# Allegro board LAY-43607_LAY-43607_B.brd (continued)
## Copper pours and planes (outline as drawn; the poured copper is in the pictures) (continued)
(no net) on TOP: 103.49,97.58 104.05,97.02 105.83,97.02 105.9,97.1 105.9,100.09 106.18,100.37 107.71,100.37 109.33,102 109.33,104.91 107.83,106.41 101.71,106.41 100.93,105.63 100.93,101.42 99.81,100.3 99.81,100.02 100.04,99.79 103.21,99.79 103.49,99.51
(no net) on TOP: 110.25,95.32 114.72,95.32 114.74,95.29 115.28,95.29 115.35,95.22 115.35,93.59 115.33,93.57 112.15,93.57 112.13,93.54 112.13,92.93 111.8,92.93 111.77,92.91 111.77,92.5 111.75,92.47 111.57,92.47 111.52,92.52 111.52,93.57 111.16,93.92 110.35,93.92 110.25,94.02
(no net) on TOP: 110.2,100.09 110.2,97.88 110.75,97.32 112.53,97.32 112.61,97.4 112.61,100.09 112.38,100.32 110.42,100.32
(no net) on TOP: 115.02,95.72 115.35,96.05 115.35,98.24 115.07,98.52 113.12,98.52 112.98,98.38 112.98,98 112.84,97.86 112.84,96.99 109.99,96.99 109.98,96.98 109.97,96.99 109.51,96.99 109.51,96.84 109.43,96.77 109.43,92.4 110.37,92.4 110.63,92.14 111.29,92.14 111.31,92.17 111.31,93.34 110.96,93.69 110.25,93.69 109.92,94.02 109.92,95.62 110.02,95.72
(no net) on TOP: 106.23,92.78 107.33,92.78 107.35,92.8 108.72,92.8 109,92.52 109,91.51 109.31,91.2 112.28,91.2 112.28,93.13 112.39,93.25 114.98,93.25 115.07,93.16 115.07,90.37 115,90.29 113.42,90.29 113.27,90.14 113.27,90.11 113.02,89.86 110.88,89.86 110.6,89.58 110.6,85.97 110.45,85.82 105.37,85.82 105.29,85.89 105.29,86.17 105.27,86.2 105.27,88.59 105.52,88.59 105.95,89.02 105.95,91.41 105.57,91.79 104.79,91.79 104.71,91.86 104.71,92.02 104.79,92.09 105.14,92.09 105.19,92.14 105.19,92.47 105.24,92.52 105.98,92.52
(no net) on BOTTOM: 112.62,82.55 112.62,81.76 112.92,81.46 112.92,78.28 113.5,77.71 118.52,77.71 118.88,78.07 118.88,79.86 118.49,80.25 115.97,80.25 115.26,80.96 113.98,80.96 113.69,81.25 113.69,82.6 113.63,82.66 112.72,82.66 112.62,82.55
CPU_LVDD on BOTTOM: 56.63,57.93 56.63,58.69 56.8,58.87 56.8,59.66 56.8,59.67 54.68,59.67 54.6,59.58 54.6,58.18 54.98,57.8 56.5,57.8
CPU_LVDD on L5_PWR: 62.98,51.33 57.9,51.33 54.47,54.75 54.52,54.75 54.52,58.94 54.72,59.15 56.55,59.15 56.88,58.82 56.88,57.68 62.34,52.21 62.98,52.21 63.23,51.96 63.23,51.58
CPU_SVDD on BOTTOM: 44.38,40.35 44.38,38.93 44.56,38.75 48.12,38.75 48.37,39.01 48.37,39.64 48.24,39.78 45.57,39.78 45.2,40.15 45.2,40.17 44.84,40.53 44.56,40.53
CPU_SVDD on L4_INT_2: 63.47,47.88 63.47,42.9 62.71,42.15 62.71,38.69 61.69,37.66 59.29,37.66 58.8,38.16 49.4,38.16 48.92,37.68 48.92,37.66 45.83,37.66 44.98,38.52 44.67,38.52 44.44,38.75 44.44,39.97 45.29,40.82 45.29,43.4 45.98,44.1 53.68,44.1 57.12,40.66 59.09,40.66 59.38,40.95 59.38,49.82 59.45,49.89 60.76,49.89 60.87,49.78 60.87,49.78 61.18,49.47 61.18,48.22 61.53,47.88
CPU_USB_HVDD on L4_INT_2: 67.65,51.24 67.65,50.68 67.04,50.07 65.77,50.07 65.02,50.08 63.66,51.45 63.66,59.94 63.19,60.41 61.49,60.41 60.98,59.9 60.98,51.5 60.99,51.49 60.99,50.53 61.62,49.9 61.62,49.14 61.85,48.91 61.85,48.91 62.51,48.25 63.93,48.25 64.15,48.04 64.44,48.04 64.44,48.04 67.11,48.04 69.35,50.27 69.35,51.24
CPU_USB_SDVDD on L4_INT_2: 67.24,50.8 67.24,52.15 67.24,52.15 66.63,52.76 66.63,59.9 66.19,60.33 64.52,60.33 64.24,60.06 64.24,59.92 64.23,59.91 64.23,51.55 65.28,50.5 66.93,50.5
CPU_USB_SVDD on L4_INT_2: 69.96,52.18 69.96,53.7 69.19,54.46 69.19,55.27 69.63,55.71 69.63,59.45 69.24,59.84 68.91,60.17 67.84,60.17 67.3,59.64 67.3,52.8 67.62,52.49 67.62,51.67 67.67,51.62 69.4,51.62
CPU_VDD on TOP: 87.01,51.67 92.1,51.67 92.5,52.07 92.5,55.76 91.94,56.32 87.6,56.32 86.85,55.57 86.85,51.82
CPU_VDD on TOP: 96,55.14 96,34.05 96.89,33.16 101.2,33.16 101.84,33.8 101.84,55.14 101.33,55.64 96.51,55.64
CPU_VDD on TOP, BOTTOM: 86.88,35.78 86.88,33.8 90.33,33.8 90.33,35.78
CPU_VDD on BOTTOM: 87.85,51.65 91.67,51.65 92.12,52.1 92.12,55.16 92.01,55.27 92.01,55.31 90.97,56.35 88.53,56.35 88.52,56.37 87.32,56.37 87.3,56.39 86.92,56.01 84.22,56.01 83.98,55.77 83.98,53.87 84.11,53.74 87.13,53.74 87.18,53.79 87.65,53.79 87.85,53.59
CPU_VDD on BOTTOM: 101.71,55.52 101.09,55.52 100.95,55.65 100.95,56.37 102.4,57.82 104.97,57.82 105.13,57.98 105.13,59.59 104.64,60.07 101.5,60.07 99.54,58.11 99.54,56.59 99.25,56.59 98.18,55.52 96.76,55.52 95.84,54.6 95.84,35.09 96.2,34.74 101.59,34.74 102.12,35.27 102.12,55.11
CPU_VDD on BOTTOM: 43.42,40.78 43.17,41.04 40.46,41.04 40.46,41.04 39.74,41.04 39.49,40.78 39.49,37.96 39.49,37.96 39.49,36.77 40.37,35.89 40.76,35.89 41.13,35.53 42.86,35.53 43.42,36.09
CPU_VDD on L4_INT_2: 91.67,51.03 84.5,51.03 83.94,51.59 83.94,55.21 82.59,56.57 78.81,56.57 74.25,61.13 74.25,61.91 74.05,62.1 71.6,62.1 71.6,62.07 70.32,60.79 61.79,60.79 60.48,62.1 57.93,62.1 57.57,61.74 57.57,61.72 55.68,59.84 50.71,59.84 47.2,56.33 47.2,49.35 44.53,46.68 44.53,41.53 43.9,40.91 43.9,38.59 44.4,38.09 45.06,38.09 45.44,37.71 45.44,35.06 45.09,34.71 40.16,34.71 39.38,35.49 39.38,43.51 40.45,44.59 40.45,49.19 40.75,49.49 42.71,49.49 43.49,50.27 43.49,53.03 42.67,53.86 42.67,57.96 44.14,59.43 44.16,59.43 48.3,63.56 53.61,63.56 57.69,67.64 57.7,67.63 66.06,67.63 66.07,67.65 66.07,66.18 70.53,66.18 71.99,67.63 78.52,67.63 84.79,61.36 89.13,61.36 89.13,59.41 92,56.54 92,55.33 92.52,54.81 92.52,51.88
CPU_VDD on L5_PWR: 69,40.05 58.64,40.05 58.61,40.08 58.61,43.3 57.94,43.97 57.94,49.18 58.57,49.8 59.34,49.8 59.5,49.95 59.5,50.77 59.78,51.05 59.79,51.03 63.15,51.03 63.55,50.64 70.68,50.64 71.5,51.45 79.58,51.45 79.66,51.37 79.66,47.61 79.81,47.46 87.2,47.46 87.2,51.48 87.08,51.6 87.28,51.81 87.28,53.2 86.57,53.92 85,53.92 84.97,53.89 84.24,53.89 83.88,54.25 83.88,56.79 84.41,57.32 100.77,57.32 102.14,55.95 102.14,48.29 101.12,47.27 101.12,41.05 101.76,40.41 101.76,32.33 101.64,32.2 90.74,32.2 89.6,33.34 86.84,33.34 82.98,37.2 80.9,37.2 75.35,42.75 70.82,42.75 70.74,42.83 70.74,43.24 70.7,43.28 69.79,43.28 69.13,42.63 69.13,40.18
CPU_VDD_I on TOP: 108.57,48.51 110.16,48.51 110.16,41.78 109.08,41.78 109.08,33.67 108.57,33.16 103.24,33.16 102.47,33.93 102.47,56.66 102.98,57.17 107.81,57.17 108.57,56.41
CPU_VDD_I on BOTTOM: 108.56,48.48 110.14,48.48 110.14,41.75 109.06,41.75 109.06,33.64 108.73,33.31 103.04,33.31 102.46,33.9 102.46,56.63 102.97,57.14 107.79,57.14 108.56,56.38
CPU_XVDD on TOP: 49.13,53.87 48.07,53.87 47.76,54.17 46.97,54.17 46.82,54.03 46.82,53.56 47.1,53.29 47.1,53.29 47.1,50.31 47.23,50.18 47.74,50.18 47.99,50.44 47.99,50.94 48.5,51.45 49.26,51.45 49.39,51.58 49.39,53.61 49.14,53.86
CPU_XVDD on TOP: 45.83,44.72 45.96,44.85 45.96,47.01 45.88,47.08 44.03,47.08 43.67,46.73 43.67,44.87 43.83,44.72
CPU_XVDD on L4_INT_2: 57.41,41.17 57.9,41.17 58.51,41.17 58.69,41.35 58.69,50.26 58.66,50.28 58.66,52.92 57.87,53.71 47.77,53.71 47.77,50.13 47.7,50.07 47.7,46.98 47.51,46.79 44.86,46.79 44.71,46.64 44.71,45.48 44.82,45.36 47.35,45.36 47.35,44.44 54.14,44.44
DDR_VTT on TOP: 36.73,19.5 36.73,20.23 39.85,20.23 39.85,18.37 39.02,18.37 39.02,17.29 38.53,17.29 38.53,3.6 53.8,3.6 53.8,1.65 36.94,1.65 36.94,19.5
DDR_VTT on TOP: 80.1,77.69 83.4,77.69 83.86,77.23 83.86,74.11 83.45,73.7 80.25,73.7 79.94,74.01 79.94,77.54
DDR_VTT on BOTTOM: 36.83,20.23 39.85,20.23 39.85,18.37 39.02,18.37 39.02,17.29 38.53,17.29 38.53,3.6 50.88,3.6 50.88,3.51 51.37,3.51 51.49,3.38 51.49,2.77 51.44,2.72 51.44,2.21 50.88,1.65 36.94,1.65 36.94,18.43 36.79,18.43 36.79,20.19
DDR_VTT on L4_INT_2: 77.99,73.35 75.73,73.35 75.6,73.47 75.6,73.93 75.78,74.11 77.38,74.11 77.53,74.26 77.53,82.85 76.02,84.36 76.02,84.42 74.29,86.15 74.29,90.37 72.74,91.93 66.19,91.93 64.28,93.83 64.28,94.54 33.01,94.54 31.48,93.01 21.71,93.01 20.53,91.84 20.56,91.81 20.56,77.78 17.39,74.61 17.39,58.82 18.53,57.68 18.53,53.61 17.39,52.47 17.39,47.13 19.16,45.36 19.16,41.03 17.39,39.26 17.39,15.05 18.26,14.19 35.88,14.19 36.04,14.35 36.04,19 36.89,19.85 39.46,19.85 39.69,19.63 39.69,9.66 39.52,9.49 39.79,9.22 39.79,5.25 38.31,3.77 23.12,3.77 18.77,8.12 14.17,8.12 13.46,8.84 13.46,16.75 13.23,16.97 13.23,77.01 13.85,77.63 16.42,77.63 17.38,78.59 17.38,93.13 28.64,104.39 64.04,104.39 64.08,104.35 68.37,104.35 81.12,91.6 85.85,91.6 87.38,90.07 87.38,85.42 86.15,84.18 86.15,83.19 84.8,81.84 84.8,74.23 84.25,73.69 82.77,73.69 82.69,73.6 78.24,73.6
FA_VL on L3_INT_1: 62.47,53.74 61.2,53.74 60.18,52.72 60.18,43.17 58.06,41.04 57.52,41.04 57.42,40.94 57.42,40.05 57.6,39.87 57.87,39.87 56.5,38.5 46.04,38.5 45.46,39.07 40.55,39.07 40.02,38.54 40.02,36.34 40.52,35.83 41.14,35.83 41.14,35.83 57.82,35.83 61.96,39.97 61.96,51.96 62.6,52.6 62.6,53.61
GVDD on TOP: 80.25,73.25 83.55,73.25 84.01,72.79 84.01,68.98 83.96,68.93 80.2,68.93 80.1,69.03 80.1,73.09
GVDD on TOP: 38.72,26.18 40.37,26.18 40.5,26.31 43.8,26.31 44.56,25.54 44.56,23.51 43.67,22.62 38.85,22.62 38.59,22.88 38.59,26.05
GVDD on TOP: 100.14,23.56 96.94,23.56 96.05,24.45 96.05,30.14 96.12,30.22 100.49,30.22 100.75,29.96 100.75,27.83 100.62,27.7 100.62,24.05
GVDD on TOP: 34.58,16.19 34.58,1.65 36.46,1.65 36.46,16.26 36.45,16.26 36.28,16.44 34.82,16.44
GVDD on BOTTOM: 100.75,26.08 96.17,26.08 95.97,26.28 95.97,30.42 96.25,30.7 100.37,30.7 100.8,30.27 100.8,26.13
GVDD on L2_GND: 58.75,39.75 58.32,40.18 54.59,40.18 54.49,40.29 54.49,40.29 53.82,40.96 46.55,40.96 44,38.42 44,35.25 43.55,34.8 43.75,34.6 43.75,30.21 43.74,30.22 38.66,30.22 37.95,29.51 37.95,22.93 38.14,22.74 39.07,22.74 39.27,22.54 39.27,19.82 39.3,19.82 39.3,16.65 37.45,16.65 36.69,15.89 35.55,15.89 35.04,15.38 35.04,5.73 35.8,4.97 38.85,4.97 39.3,4.51 39.3,3.32 40.32,2.3 101.78,2.3 101.78,6.41 104.21,8.84 104.21,18.82 103.56,19.47 103.56,19.82 103.56,20.14 99.82,23.89 99.82,28.81 99.32,29.31 94.35,29.31 93.28,30.38 93.28,30.38 92.74,30.92 89.65,30.92 89.63,30.9 86.27,34.26 86.1,34.26 84.96,35.39 84.96,37.06 81.62,40.41 79.48,40.41 79.02,39.95 77.93,39.95 77.47,40.41 73.58,40.41 73.06,39.89 73.06,37.75 69.71,37.75 68.05,39.4 58.88,39.4 58.75,39.54
GVDD on L4_INT_2: outline of 84 points within 25.49,21.61 83.29,93.79
OVDD on TOP: 57.85,81.53 61.15,81.53 61.61,81.07 61.61,77.94 61.2,77.54 58,77.54 57.69,77.84 57.69,81.37
OVDD on TOP: 13.84,80.85 15.12,80.85 15.12,80.17 16.67,78.61 16.67,71.5 17.28,70.89 17.28,58.83 17.62,58.49 17.62,57.57 17.53,57.48 15.21,57.48 15.12,57.57 15.12,68.36 13.84,69.63
OVDD on BOTTOM: 88.58,38.63 88.38,38.83 86.42,38.83 86.12,39.13 86.12,39.69 86.47,40.05 87.77,40.05 87.95,40.23 87.95,41.67 87.59,42.03 86.22,42.03 85.86,42.38 85.86,45.15 86.04,45.33 94.12,45.33 95.08,44.37 95.08,38.57 95.46,38.19 95.46,35.06 95.2,34.8 94.1,34.8 93.71,35.19 93.71,36.7 93.74,36.72 93.74,37.99 92.19,37.99 90.94,39.23 90.13,39.23 89.6,38.7 89.6,36.36 89.57,36.34 88.76,36.34 88.58,36.52
OVDD on BOTTOM: 25.27,84.73 25.01,84.99 20.55,84.99 19.16,86.38 14.32,86.38 13.86,85.91 13.86,78.99 14,78.85 15.64,78.85 16.13,79.34 16.13,84.35 16.42,84.64 18.95,84.64 22.12,81.47 22.12,78.45 22.47,78.1 24.72,78.1 25.27,78.65
OVDD on BOTTOM: 84.6,51.91 85.72,51.91 85.92,51.7 86.75,51.7 86.95,51.91 86.95,53.22 86.62,53.55 85.07,53.55 84.36,52.84 84.36,52.19 84.6,51.95
OVDD on BOTTOM: 32.36,67.79 32.57,67.59 33.33,67.59 33.36,67.57 33.63,67.57 34.1,68.03 34.1,70.47 34.1,70.47 34.4,70.77 34.4,71.44 34.16,71.67 33.51,71.67 33.36,71.53 33.36,70.98 32.74,70.98 32.36,70.6
OVDD on BOTTOM: 88.77,88.98 84.16,88.98 79.06,94.07 74.13,94.07 73.34,94.86 73.34,97.43 73.7,97.79 73.7,98.69 73.83,98.82 76.37,98.82 76.44,98.75 76.44,98.17 76.9,97.7 79.41,97.7 79.5,97.8 79.5,98.76 79.57,98.83 80.65,98.83 80.73,98.75 80.73,98.05 80.95,97.83 82.59,97.83 82.68,97.91 82.68,98.7 82.84,98.86 83.72,98.86 83.93,98.64 83.93,98.32 84.26,97.99 85.37,97.99 85.62,98.25 85.62,98.61 85.91,98.89 86.68,98.89 86.68,109.13 85.47,110.34 85.47,112.15 86,112.68 87.64,112.68 88.15,112.17 88.15,97.43 87.88,97.16 80.95,97.16 80.75,96.95 80.75,96.35 81.12,95.98 86.77,95.98 86.84,96.05 87.19,96.05 87.53,95.71 87.53,94.94 84.91,92.32 84.91,91.21 85.75,90.38 87.11,90.38 87.16,90.43 88.52,90.43 88.94,90.01 88.94,89.14
OVDD on BOTTOM: 54.01,60.01 55.51,60.01 55.61,60.11 55.61,62.09 54.91,62.79 54.91,67.44 56.63,69.16 56.63,77.04 57.67,78.08 60.63,78.08 60.82,78.27 60.82,82.03 60.67,82.19 54.7,82.19 53.15,80.64 53.15,68.91 52.08,67.84 52.02,67.84 48.99,64.81 48.79,64.61 44.85,64.61 43.29,63.05 42.49,63.05 41.92,62.48 41.92,62.27 41.92,62.27 41.92,61.41 42.02,61.31 42.98,61.31 43.21,61.55 43.21,62 43.36,62.15 44.16,62.15 44.18,62.17 45.12,62.17 45.28,62.33 45.28,62.87 45.3,62.84 46.42,62.84 46.68,62.59 46.68,62.17 46.92,62.17 47.84,61.26 48.96,61.26 49.34,60.88 51.75,60.88 52.87,59.76 53.76,59.76
OVDD on L3_INT_1: 71.23,51.22 71.23,50.82 71.11,50.69 70.47,50.69 69.2,49.42 69.2,46.63 69.84,45.99 69.84,42.05 69.45,41.67 68.44,41.67 67.1,40.34 67.1,29.51 66.49,28.9 44.05,28.9 43.6,29.35 43.6,29.43 41.41,31.61 41.38,31.61 41.38,34.63 41.89,35.15 57.76,35.15 62.44,39.83 62.44,51.83 62.8,52.19 62.8,52.39 63.08,52.67 69.58,52.67 69.58,51.73 69.94,51.38 71.08,51.38
OVDD on L4_INT_2: 86.76,113.45 19.99,113.45 13.85,107.32 13.85,78.61 14.09,78.37 16.38,78.37 16.78,78.77 16.78,95.88 16.72,95.94 25.79,105 68.84,105 74.97,98.88 74.97,98.85 78.22,95.59 78.23,95.59 81.77,92.06 84.72,92.06 86.73,94.07 92.53,94.07 95.94,90.67 95.94,81.18 96.1,81.03 96.1,61.61 96.16,61.55 96.16,56.02 94.79,54.66 94.79,42.2 96.16,40.84 96.16,37.25 105.49,27.92 105.49,20.46 107.55,18.4 107.55,8.07 107.14,7.66 105.76,7.66 103.44,9.98 103.44,26.69 95.04,35.09 95.04,38.51 94.47,39.08 91.07,39.08 90.91,39.24 90.91,43.61 89.05,45.46 85.31,45.46 85.13,45.65 85.13,46.81 84.96,46.99 80.81,46.99 80.49,46.67 80.49,40.32 81.44,39.37 86.4,39.37 88.46,37.32 88.46,33.94 98.59,23.81 98.59,7.73 102.42,3.9 110.86,3.9 112,5.04 112,15.26 113.01,16.27 125.4,16.27 126.51,17.38 126.51,28.78 126.36,28.93 113.95,28.93 100.45,42.44 100.45,55.54 102.17,57.26 102.17,97.93 101.21,98.89 100.44,98.89 97.82,101.51 97.82,110.34 94.22,113.94 86.9,113.94 86.76,113.8
OVDD on L4_INT_2: 52.44,81.87 66.19,81.87 66.63,81.43 66.63,78.81 64.9,77.08 63.91,77.08 63.85,77.02 58.72,77.02 58.17,76.47 58.17,73.71 53.65,69.19 53.65,68.46 52.95,67.77 52.94,67.78 43.8,67.78 42.4,66.38 39.42,66.38 37.56,64.52 37.56,60.97 37.01,60.43 36.08,60.43 35.62,59.96 35.62,53.05 38.38,50.29 38.05,49.97 38.05,42.79 38.84,42 38.84,35.63 40.44,34.02 44.16,34.02 44.16,30.56 38.13,30.56 32.5,36.2 32.5,64.9 32.46,64.94 32.44,64.94 32.44,68.62 32.44,68.62 32.25,68.81 32.25,70.5 32.74,70.98 32.74,71.02 33.33,71.62 45.48,71.62 46.15,72.29 46.15,76.62 46.34,76.8 47.31,76.8 48.52,78.01 51.29,78.01 52.11,78.83 52.11,81.55
OVDD on L5_PWR: outline of 83 points within 77.24,15.97 126.2,74.03
OVDD on L5_PWR: 74.51,98.86 86.36,98.86 87.29,97.93 87.29,96.17 74.79,83.67 67.74,83.67 66.71,82.64 66.71,80.94 66.6,80.84 63.51,80.84 60.64,77.97 58.24,77.97 57.98,78.23 57.98,86.16 58.48,86.66 67.83,86.66 68.11,86.95 68.11,92.47
SW1LX on TOP: 62.72,85.01 62.72,81.84 64.12,81.84 64.63,81.33 64.63,79.69 65.01,79.31 65.26,79.31 65.39,79.43 65.39,80.83 66.03,81.46 66.03,83.23 64.25,85.01
SW2LX on TOP: 62.6,81.07 62.6,78.02 64.87,78.02 65.26,78.42 65.26,78.54 64.25,79.56 64.25,81.07
SW3LX on TOP: 62.72,74.08 63.72,74.08 63.99,74.35 63.99,75.75 64.63,76.38 64.63,77.02 64.25,77.4 62.72,77.4
SW5LX on TOP: 77.8,73.88 77.33,74.35 77.33,75.37 76.82,75.88 76.69,75.88 76.69,72.02 77.05,72.02 77.17,71.9 77.17,70.34 77.24,70.27 79.11,70.27 79.17,70.33 79.18,70.33 79.18,73.72 79.02,73.88
SW6LX on TOP: 77.46,77.15 79.11,77.15 79.11,74.35 77.71,74.35 77.71,75.5 76.95,76.26 76.95,76.64
SW7LX on TOP: 79.03,80.94 77.96,80.94 77.33,80.31 77.33,77.77 79.03,77.77
USB1_ISO_VOUT on TOP (solid shape): 112.61,100.09 112.61,99.45 112.61,99.22 112.61,97.99 112.58,97.96 112.58,97.37 112.53,97.32 110.75,97.32 110.2,97.88 110.2,100.09 110.42,100.32 112.38,100.32
USB1_ISO_VOUT on BOTTOM: 110.35,100.27 110.35,100.22 109.94,99.81 109.94,98.21 110.02,98.14 112.43,98.14 112.43,100.07 112.46,100.09 112.28,100.27
USB1_ISO_VOUT on L3_INT_1: 107.51,100.86 110.08,98.29 112.28,98.29 112.88,98.89 112.88,100.19 112.44,100.63 110.74,100.63 110.28,101.09 110.28,106.66 110.32,106.7 110.32,107.39 109.36,108.35 109.36,110.81 108.85,111.32 103.26,111.32 101.91,109.97 101.91,101.39 104.2,101.39 104.2,101.37 104.71,100.86
USB2_ISO_VOUT on TOP (solid shape): outline of 518 points within 99.81,97.02 109.33,106.41
USB2_ISO_VOUT on BOTTOM: 103.95,99.71 103.95,99.66 103.54,99.26 103.54,97.65 103.62,97.58 106.03,97.58 106.03,99.51 106.06,99.53 105.88,99.71

Small or netless copper shapes (teardrops, artwork), in the pictures only: 1 on TOP

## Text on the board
BOTTOM: 13 | L6_SS | 170-43607 REV B
Board Geometry/Soldermask Bottom: 14 | SECONDARY SOLDERMASK
Ref Des/Silkscreen Bottom: $ | D | C | # | F | A | B | E | S3 | S2 | 15 | SECONDARY SILKSCREEN
User.Comments: 1 OF 1 | TEST PROBE | 1/1 | 1 | 2
TOP: 04 | L1_PS
Board Geometry/Soldermask Top: 03 | PRIMARY SOLDERMASK
Ref Des/Silkscreen Top: SIN | SOUT | 3V3 | CTS | GND | RST | PWR | (UART1) | (UART2 & UART4) | $ | % | D | MISO | MOSI | SCK | AN | CS | A | S | AA | * | @ | B | TX | INT | RX | PWM | SDA | 5V | SCL | S3 | ~ | CLK | CS1 | CS2 | CS3 | S2 | ON | 02 | PRIMARY SILKSCREEN | X-FRWYLS1046A
L2_GND: 05 | L2_GND_1
L3_INT_1: 06 | L3_INT_1
L4_INT_2: 07 | L4_INT_2
L5_PWR: 08 | L5_PWR_1
XSECTION_CHART: *  SURFACE | *  DIELECTRIC | L1 TOP CONDUCTOR | L2 L2_GND PLANE | L3 L3_INT_1 CONDUCTOR | L4 L4_INT_2 CONDUCTOR | L5 L5_PWR PLANE | L6 BOTTOM CONDUCTOR | DESIGN CROSS SECTION CHART | ___________________________ | TOTAL THICKNESS 59.674 MIL | STACKUP TABLE | Unit = Mils | # | 1 | 2 | 3 | 4 | 5 | 6 | NAME | TOP | L2_GND | L3_INT_1 | L4_INT_2 | L5_PWR | BOTTOM | TYPE | SURFACE | DIELECTRIC | CONDUCTOR | PLANE | MATERIAL | AIR | FR-4 | 1/2OZ_PLATED_COPPER_FOIL | 1OZ_COPPER | 1/2OZ_COPPER | 1/2OZ_COPPER_PLATED_FOIL | TOTAL THICKNESS | THICKNESS | 0 | 0.5 | 1.2 | 3.35 | 2.99 | 0.65 | 4.2 | 31.5 | 59.67 | TOLERANCE | +0/-0 | 1-6 | SCALE: NONE | BOARD THICKNESS TOLERANCE +/-10% | 8 | 22 | 16 | 19 | DETAIL | IMPEDANCE REQUIREMENTS | IMPEDANCE TOLERANCE IS 10% | LAYER STACKUP | B | A
DIMENSION: BOARD CUTOUT | PRIMARY DATUM | GRID ORIGIN
BODY_CENTER: 01 | PASTEMASK TOP
DISPLAY_BOTTOM: 16 | SECONDARY PASTEMASK
User.9: OF 14
User.12: 22. THIS FAB_VIAFILL.ART SHOWS LOCATIONS OF VIA-IN-PAD TO BE FILLED. | 1/1 | 2
User.13: 1/1 | 3
User.14: REPLACED MICRO-AB J45 | 03-19-19 | L.P. | B
User.17: TRACE WIDTH | (MILS) | IMPEDANCE | (OHMS) | TRACE SPACING | "AIR GAP" | L1_PS | L3_INT_1 | L4_INT_2 | L6_SS | 5.4 | 4.2 | 50 | 4.1 | 5.2 | 4.5 | 6.0 | 90 | 4.9 | 3.7 | 7.7 | 10.9 | 100 | LAYERS | SINGLE ENDED | DIFFERENTIAL
User.20: FIGURE | FINISHED_SIZE | 8.0 | 8.1 | 10.0 | 10.1 | 12.0 | 18.0 | 28.0 | 35.0 | 38.0 | 40.0 | 41.0 | 63.0 | 91.0 | 126.0 | 165.0 | 30.0 | 43.0 | 128.0 | 60.0x24.0 | 71.0x24.0 | 131.0x40.0 | 139.0x40.0 | 159.0x40.0 | DRILL CHART: TOP to BOTTOM | ALL UNITS ARE IN MILS | TOLERANCE_DRILL | +0.0/-8.0 | +0.0/-8.1 | +0.0/-10.0 | +0.0/-10.1 | +0.0/-12.0 | +2.0/-2.0 | +3.0/-3.0 | +4.0/-2.0 | PLATED | NON-PLATED | QTY | 1187 | 571 | 554 | 87 | 450 | 8 | 34 | 60 | 4 | 58 | 6 | 10 | 2 | 12 | 1 | 3068 | TOTAL HOLES:
User.26: USB_MicroAB_Console
